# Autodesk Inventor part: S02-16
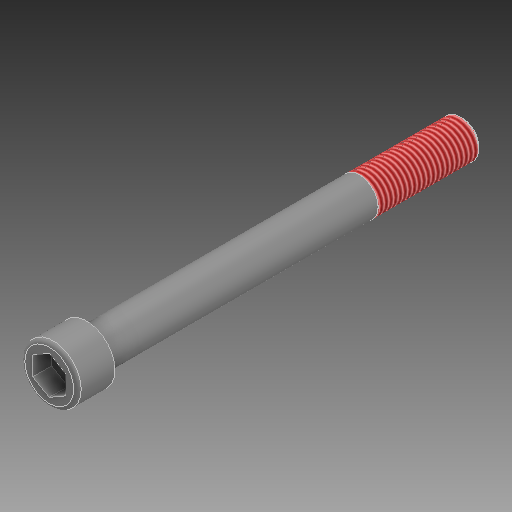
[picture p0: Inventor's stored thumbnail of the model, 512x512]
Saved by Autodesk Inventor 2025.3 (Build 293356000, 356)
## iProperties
Manager: ISO 4762 (DIN 912)
Created: 2025-04
Part Number: S02-16
Material: Všeobecné
Document SubType Name: Modeling
Designer: Patrik
Density: 1 g/cm^3
Appearance: Výchozí
Description: Imbusový šroub s válcovou hlavou
Stock Number: E 1200/16x160
User Status: 12.9
Author: Patrik
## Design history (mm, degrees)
feature "Base1"
feature "Závit1" dims "d0" = 42.775, "d1" = 0
node "Těleso1"
